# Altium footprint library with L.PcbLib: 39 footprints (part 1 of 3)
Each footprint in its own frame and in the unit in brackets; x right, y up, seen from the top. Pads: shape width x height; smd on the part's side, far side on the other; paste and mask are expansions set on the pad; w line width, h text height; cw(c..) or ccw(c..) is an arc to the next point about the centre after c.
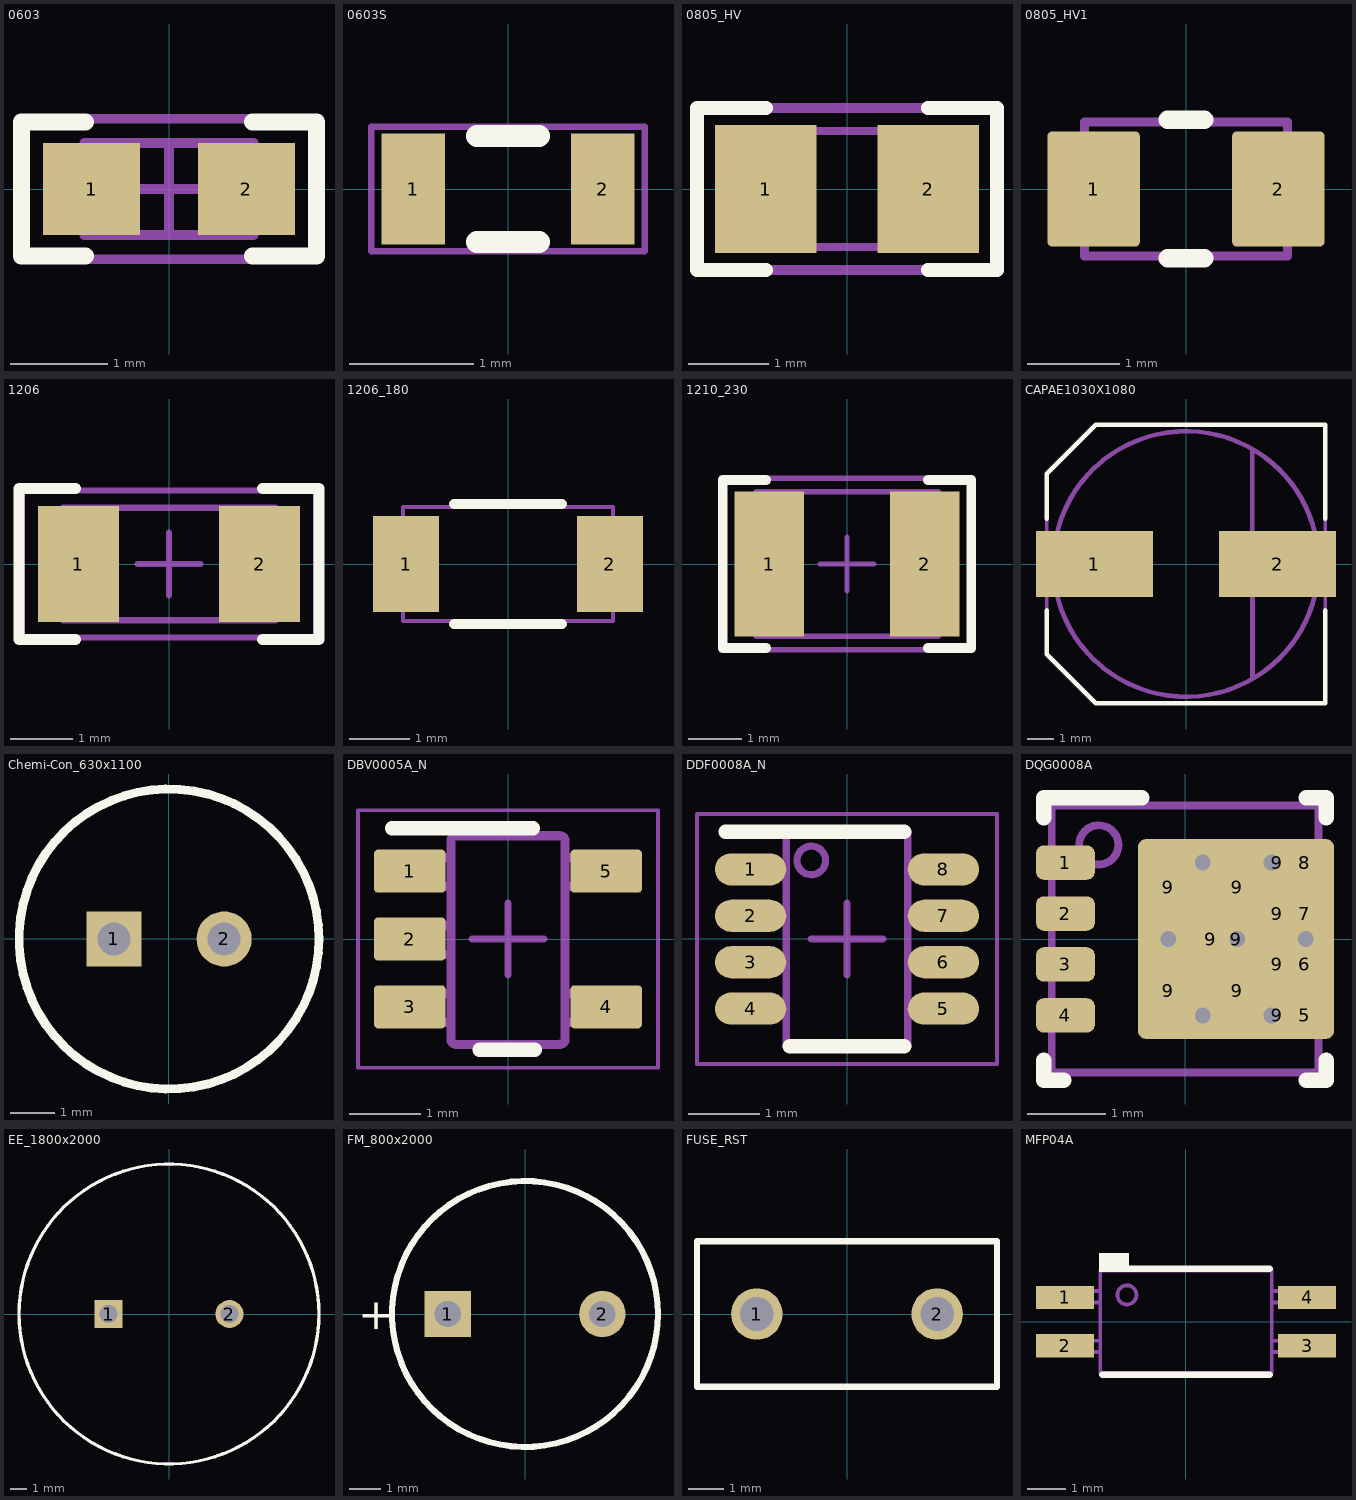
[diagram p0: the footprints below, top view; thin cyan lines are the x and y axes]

## 0603 [mm] "0603 from SM-752 data"
height 1
pads (2):
  rect 1x0.95 smd: 1(-0.8,0) 2(0.8,0)
Top Overlay:
  lines w0.178: -0.864,-0.691 -1.524,-0.691 -1.524,0.693 -0.864,0.693 ; 0.864,-0.691 1.524,-0.691 1.524,0.693 0.864,0.693
Mechanical 5:
  lines w0.1: -1.55,-0.725 1.55,-0.725 1.55,0.725 -1.55,0.725 -1.55,-0.725
  text ".Designator" at -1.397,-0.381 h0.76
Mechanical 13:
  lines w0.1: -0.55,-0.475 -0.55,0.475 ; 0.55,-0.475 0.55,0.475 ; -0.875,-0.475 -0.875,0.475 0.875,0.475 0.875,-0.475 -0.875,-0.475
Mechanical 15:
  lines w0.1: -0.475,0 0.475,0 ; 0,-0.475 0,0.475 ; -1.55,-0.725 -1.55,0.725 1.55,0.725 1.55,-0.725 -1.55,-0.725
3D body: height 1, standoff 0, extent 0.551,-0.474 0.874,0.474
3D body: height 1, standoff 0, extent -0.549,-0.474 0.549,0.474
3D body: height 1, standoff 0, extent -0.874,-0.474 -0.551,0.474

## 0603S [mil]
height 39.37
pads (2):
  rect 20x35 smd: 1(-30,0) 2(30,0)
Top Overlay:
  lines w7: -9.84,-16.73 9.84,-16.73 ; -9.84,16.73 9.84,16.73
Mechanical 5:
  lines w1.97: -43.31,-19.68 43.31,-19.68 43.31,19.68 -43.31,19.68 -43.31,-19.68
  text ".Designator" at -32.48,-8.86 h18
3D body: height 39.37, standoff 0, extent -34.43,-18.68 -21.67,18.68
3D body: height 39.37, standoff 0, extent -21.63,-18.68 21.63,18.68
3D body: height 39.37, standoff 0, extent 21.67,-18.68 34.43,18.68

## 0805_HV [mil] "0805 with 30mil clearance between pads"
height 57.09
pads (2):
  rect 50x63 smd: 1(-40,0) 2(40,0)
Top Overlay:
  lines w7: -40,-40 -74,-40 -74,0 -74,40 -40,40 ; 40,-40 74,-40 74,0 74,40 40,40
Mechanical 5:
  lines w5: -74,-40 -74,40 74,40 74,-40 -74,-40
  text ".Designator" at -64,-17 h35
Mechanical 13:
  lines w3.94: -25.59,-28.54 -25.59,28.54 ; 25.59,-28.54 25.59,28.54 ; -43.31,-28.54 -43.31,28.54 43.31,28.54 43.31,-28.54 -43.31,-28.54
3D body: height 57.09, standoff 0, extent 25.61,-28.52 43.29,28.52
3D body: height 57.09, standoff 0, extent -25.57,-28.52 25.57,28.52
3D body: height 57.09, standoff 0, extent -43.29,-28.52 -25.61,28.52

## 0805_HV1 [mm] "Custom footprint based on analyzing multiple manufacturer recommendations"
height 1.45
pads (2):
  rrect10% 1x1.25 smd: 1(-1,0) 2(1,0)
Top Overlay:
  lines w0.2: -0.2,-0.75 0.2,-0.75 ; -0.2,0.75 0.2,0.75
Mechanical 5:
  lines w0.1: -1.1,-0.725 1.1,-0.725 1.1,0.725 -1.1,0.725 -1.1,-0.725
  text ".Designator" at -0.925,-0.25 h0.51
3D body "0805_CapMax.stp": height 1.45, standoff 0, extent -1.1,-0.725 1.1,0.725

## 1206 [mm] "1206 from SM-752 data"
height 1.35
pads (2):
  rect 1.3x1.85 smd: 1(-1.45,0) 2(1.45,0)
Top Overlay:
  lines w0.178: -1.5,-1.21 -2.4,-1.21 -2.4,1.21 -1.5,1.21 ; 1.5,-1.21 2.4,-1.21 2.4,1.21 1.5,1.21
Mechanical 5:
  lines w0.1: -1.7,-0.9 -1.7,0.9 1.7,0.9 1.7,-0.9 -1.7,-0.9
Mechanical 13:
  lines w0.1: -1.2,-0.9 -1.2,0.9 ; 1.2,-0.9 1.2,0.9 ; -1.7,-0.9 -1.7,0.9 1.7,0.9 1.7,-0.9 -1.7,-0.9
Mechanical 15:
  lines w0.1: -0.5,0 0.5,0 ; 0,-0.5 0,0.5 ; -2.35,-1.175 -2.35,1.175 2.35,1.175 2.35,-1.175 -2.35,-1.175
3D body: height 1.35, standoff 0, extent 1.201,-0.899 1.699,0.899
3D body: height 1.35, standoff 0, extent -1.199,-0.899 1.199,0.899
3D body: height 1.35, standoff 0, extent -1.699,-0.899 -1.201,0.899

## 1206_180 [mm] "1206_180"
height 1.8
pads (2):
  rect 1.1x1.6 smd: 1(-1.7,0) 2(1.7,0)
Top Overlay:
  lines w0.17: -0.9,-1 0.9,-1 ; -0.9,1 0.9,1
Mechanical 5:
  lines w0.07: -1.75,-0.95 1.75,-0.95 1.75,0.95 -1.75,0.95 -1.75,-0.95
  text ".Designator" at -1.5,-0.4 h0.81
3D body: height 1.8, standoff 0, extent -1.749,-0.949 -1.301,0.949
3D body: height 1.8, standoff 0, extent -1.299,-0.949 1.299,0.949
3D body: height 1.8, standoff 0, extent 1.301,-0.949 1.749,0.949

## 1210_230 [mm] "1210"
height 2.3
pads (2):
  rect 1.3x2.7 smd: 1(-1.45,0) 2(1.45,0)
Top Overlay:
  lines w0.178: -1.511,-1.568 -2.316,-1.568 -2.316,1.568 -1.511,1.568 ; 1.511,-1.568 2.316,-1.568 2.316,1.568 1.511,1.568
Mechanical 5:
  lines w0.1: -1.7,-1.35 -1.7,1.35 1.7,1.35 1.7,-1.35 -1.7,-1.35
  text ".Designator" at -1.4,-0.375 h0.76
Mechanical 13:
  lines w0.1: -1.2,-1.35 -1.2,1.35 ; 1.2,-1.35 1.2,1.35 ; -1.7,-1.35 1.7,-1.35 1.7,1.35 -1.7,1.35 -1.7,-1.35
Mechanical 15:
  lines w0.1: -0.5,0 0.5,0 ; 0,-0.5 0,0.5 ; -2.35,-1.6 2.35,-1.6 2.35,1.6 -2.35,1.6 -2.35,-1.6
3D body: height 2.3, standoff 0, extent 1.201,-1.349 1.699,1.349
3D body: height 2.3, standoff 0, extent -1.199,-1.349 1.199,1.349
3D body: height 2.3, standoff 0, extent -1.699,-1.349 -1.201,1.349

## CAPAE1030X1080 [mm] "10.3 x 10.3 mm base"
height 10.8
pads (2):
  rect 4.4x2.5 smd: 1(-3.45,0) 2(3.45,0)
Top Overlay:
  lines w0.178: -5.25,-1.75 -5.25,-3.4 -3.4,-5.25 0,-5.25 5.25,-5.25 5.25,-1.75 ; -5.25,1.7 -5.25,3.4 -3.4,5.25 0,5.25 5.25,5.25 5.25,1.7
Mechanical 5:
  lines w0.127: -5.25,-3.4 -3.4,-5.25 0,-5.25 5.25,-5.25 5.25,5.25 0,5.25 -3.4,5.25 -5.25,3.4 -5.25,-3.4
Mechanical 13:
  circle w0.178: c0,0 r5
  lines w0.178: 2.5,-4.33 ccw(c0,0) 2.5,4.33 ; 2.5,4.325 2.505,-4.3
3D body: height 10.5, standoff 10.4, extent 2.505,-4.34 5.011,4.34
3D body: height 10.5, standoff 1, extent -5.249,-5.249 5.249,5.249
3D body: height 1, standoff 0, extent -5.251,-5.251 5.251,5.251

## Chemi-Con_630x1100 [mm] "TH, 2-Leads, Dia 6.3mm, Pin Spacing 2.5mm"
height 12.5
pads (2):
  rect 1.25x1.25 hole 0.75: 1(-1.25,0)
  round 1.25 hole 0.75: 2(1.25,0)
Top Overlay:
  circle w0.2: c0,0 r3.4
Mechanical 5:
  circle w0.1: c0,0 r3.4
3D body "KMG_630X1100.stp": height 12.51, standoff -4, extent -3.4,-3.4 3.41,3.4

## DBV0005A_N [mm] "SOT23, 5-Leads, Body 2.9x1.6mm, Pitch 0.95mm, Lead Span 2.8mm, IPC Medium Density"
height 1.45
pads (5):
  rrect17% 1x0.6 smd: 1(-1.375,0.95) 2(-1.375,0) 3(-1.375,-0.95) 4(1.375,-0.95) 5(1.375,0.95)
Top Overlay:
  lines w0.2: -1.625,1.55 0.35,1.55 ; -0.4,-1.55 0.375,-1.55
Mechanical 5:
  lines w0.127: -0.801,1.371 cw(c-0.725,1.37) -0.725,1.446 ; -0.801,1.37 -0.801,1.371 ; -0.801,1.37 -0.801,-1.399 -0.801,-1.4 ccw(c-0.725,-1.399) -0.725,-1.475 ; -0.725,-1.475 0.723,-1.475 0.724,-1.475 ccw(c0.723,-1.399) 0.799,-1.4 0.799,-1.399 0.799,1.37 ; -0.725,-1.475 -0.725,-1.475 ; -0.725,1.446 -0.725,1.446 ; -0.725,1.446 0.723,1.446 0.724,1.446 cw(c0.723,1.37) 0.799,1.371 ; 0.799,1.37 0.799,1.371 ; -1.423,-1.167 -1.423,-0.767 -1.199,-0.767 -1.105,-0.767 -1.088,-0.767 -0.835,-0.767 -0.801,-0.767 -0.801,-1.167 -0.835,-1.167 -1.088,-1.167 -1.105,-1.167 -1.199,-1.167 -1.423,-1.167 ; -1.423,-0.215 -1.423,0.186 -1.199,0.186 -1.105,0.186 -1.088,0.186 -0.835,0.186 -0.801,0.186 -0.801,-0.215 -0.835,-0.215 -1.088,-0.215 -1.105,-0.215 -1.199,-0.215 -1.423,-0.215 ; -1.423,0.738 -1.423,1.138 -1.199,1.138 -1.105,1.138 -1.088,1.138 -0.835,1.138 -0.801,1.138 -0.801,0.738 -0.835,0.738 -1.088,0.738 -1.105,0.738 -1.199,0.738 -1.423,0.738 ; 0.799,-1.167 0.834,-1.167 1.087,-1.167 1.103,-1.167 1.198,-1.167 1.422,-1.167 1.422,-0.767 1.198,-0.767 1.103,-0.767 1.087,-0.767 0.834,-0.767 0.799,-0.767 0.799,-1.167 ; 0.799,0.738 0.834,0.738 1.087,0.738 1.103,0.738 1.198,0.738 1.422,0.738 1.422,1.138 1.198,1.138 1.103,1.138 1.087,1.138 0.834,1.138 0.799,1.138 0.799,0.738
Mechanical 15:
  lines w0.05: -2.1,-1.8 -2.1,1.8 2.1,1.8 2.1,-1.8 -2.1,-1.8
  lines w0.1: -0.5,0 0.5,0 ; 0,-0.5 0,0.5
3D body "DBV0005A.stp": height 1.09, standoff 0, extent -1.422,-1.46 1.422,1.461

## DDF0008A_N [mm] "TSOP, 8-Leads, Body 2.90x1.60mm, Pitch 0.65mm, IPC Medium Density"
height 1.1
pads (8):
  oval 1x0.45 smd: 1(-1.35,0.975) 2(-1.35,0.325) 3(-1.35,-0.325) 4(-1.35,-0.975) 5(1.35,-0.975) 6(1.35,-0.325) 7(1.35,0.325) 8(1.35,0.975)
Top Overlay:
  lines w0.2: -1.7,1.5 0.8,1.5 ; -0.8,-1.5 0.8,-1.5
Mechanical 5:
  circle w0.1: c-0.5,1.1 r0.2
  lines w0.1: -0.85,-1.5 -0.85,1.5 0.85,1.5 0.85,-1.5 -0.85,-1.5
Mechanical 15:
  lines w0.05: -2.1,-1.75 -2.1,1.75 2.1,1.75 2.1,-1.75 -2.1,-1.75
  lines w0.1: -0.5,0 0.5,0 ; 0,-0.5 0,0.5
3D body "DDF0008A.stp": height 1.1, standoff 0, extent -1.409,-1.45 1.409,1.45

## DQG0008A [mm] "SMD, 8-Leads, Body 3.3x3.3mm, Pitch 0.65mm"
height 1.1
pads (18):
  rrect45% 0.75x0.44 smd paste-0.05 mask-0.05: 1(-1.525,0.975) 2(-1.525,0.325) 3(-1.525,-0.325) 4(-1.525,-0.975) 5(1.525,-0.975) 6(1.525,-0.325) 7(1.525,0.325) 8(1.525,0.975)
  rrect50% 0.676x1.125 on Top Paste: 9(-0.212,-0.663) 9(-0.212,0.662) 9(0.664,-0.663) 9(0.664,0.662)
  rrect50% 1.775x2.45 on Top Solder: 9(0.327,0)
  rrect8% 2.5x2.55 smd paste-1.5 mask-1.5: 9(0.65,0)
  rrect50% 0.5x0.34 on Top Solder: 9(1.175,-0.975) 9(1.175,-0.325) 9(1.175,0.325) 9(1.175,0.975)
via 1.54,0 diameter 0.5 hole 0.2
via -0.212,0 diameter 0.5 hole 0.2
via 0.664,0 diameter 0.5 hole 0.2
via 0.226,-0.975 diameter 0.5 hole 0.2
via 1.102,-0.975 diameter 0.5 hole 0.2
via 1.102,0.975 diameter 0.5 hole 0.2
via 0.226,0.975 diameter 0.5 hole 0.2
Top Overlay:
  lines w0.2: -1.8,-1.55 -1.8,-1.8 -1.55,-1.8 ; -1.8,1.55 -1.8,1.8 -0.55,1.8 ; 1.55,-1.8 1.8,-1.8 1.8,-1.55 ; 1.55,1.8 1.8,1.8 1.8,1.55
Mechanical 5:
  circle w0.1: c-1.1,1.2 r0.25
  lines w0.1: -1.7,-1.7 -1.7,1.7 1.7,1.7 1.7,-1.7 -1.7,-1.7
3D body "DQG0008A.stp": height 1.1, standoff 0, extent -1.65,-1.65 1.65,1.65

## EE_1800x2000 [mm] "PANASONIC"
height 22
pads (2):
  rect 1.75x1.75 hole 1.1: 1(-3.75,0)
  round 1.75 hole 1.1: 2(3.75,0)
Top Overlay:
  circle w0.2: c0,0 r9.305
Mechanical 5:
  circle w0.1: c0,0 r9.25
3D body "EE_1800x2000.stp": height 22.01, standoff -4, extent -9.177,-9.235 9.225,9.235

## FM_800x2000 [mm] "PANASONIC"
height 22
pads (2):
  rect 1.5x1.5 hole 0.85: 1(-2.5,0)
  round 1.5 hole 0.85: 2(2.5,0)
Top Overlay:
  circle w0.2: c0,0 r4.3
  text "+" at -5.4,-0.5 h1.02
Mechanical 5:
  circle w0.1: c0,0 r4.25
  text ".Designator" at -1.8,-0.5 h1.02
  text "+" at -5.4,-0.5 h1.02
3D body "FM_800x2000.stp": height 22.01, standoff -4, extent -4.217,-4.243 4.244,4.243

## FUSE_RST [mm] "Bel Fuse RST series May2012D"
height 7.9
pads (2):
  round 1.45 hole 0.95: 1(-2.54,0) 2(2.54,0)
Top Overlay:
  lines w0.178: -4.225,-2.05 4.225,-2.05 4.225,2.05 -4.225,2.05 -4.225,-2.05
Mechanical 5:
  lines w0.1: -4.225,-2.05 -4.225,2.05 4.225,2.05 4.225,-2.05 -4.225,-2.05
3D body "Fuse_RST.stp": height 7.9, standoff -4.3, extent -4.225,-2.05 4.225,2.05

## MFP04A [mm] "FAIRCHILD optocoupler"
height 2.39
pads (4):
  rect 1.52x0.61 smd: 1(-3.175,0.635) 2(-3.175,-0.635) 3(3.175,-0.635) 4(3.175,0.635)
Top Overlay:
  rectangle: -2.28,1.3 -1.5,1.8
  lines w0.17: -2.2,-1.4 2.2,-1.4 ; -2.2,1.385 2.2,1.385
Mechanical 5:
  circle w0.1: c-1.55,0.7 r0.25
  lines w0.1: -2.25,-0.8 -3.6,-0.8 -3.6,-0.5 -2.25,-0.5 ; -2.25,0.5 -3.6,0.5 -3.6,0.8 -2.25,0.8 ; 2.25,-0.8 3.6,-0.8 3.6,-0.5 2.25,-0.5 ; 2.25,0.5 3.6,0.5 3.6,0.8 2.25,0.8 ; -2.25,-1.345 -2.25,1.345 2.25,1.345 2.25,-1.345 -2.25,-1.345
3D body: height 1.2, standoff 0, extent 2.251,0.501 3.599,0.799
3D body: height 1.2, standoff 0, extent 2.251,-0.799 3.599,-0.501
3D body: height 1.2, standoff 0, extent -3.599,0.501 -2.251,0.799
3D body: height 1.2, standoff 0, extent -3.599,-0.799 -2.251,-0.501
3D body: height 2.39, standoff 0, extent -2.249,-1.344 2.249,1.344
3D body: height 2.39, standoff 2, extent -1.799,0.451 -1.301,0.949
